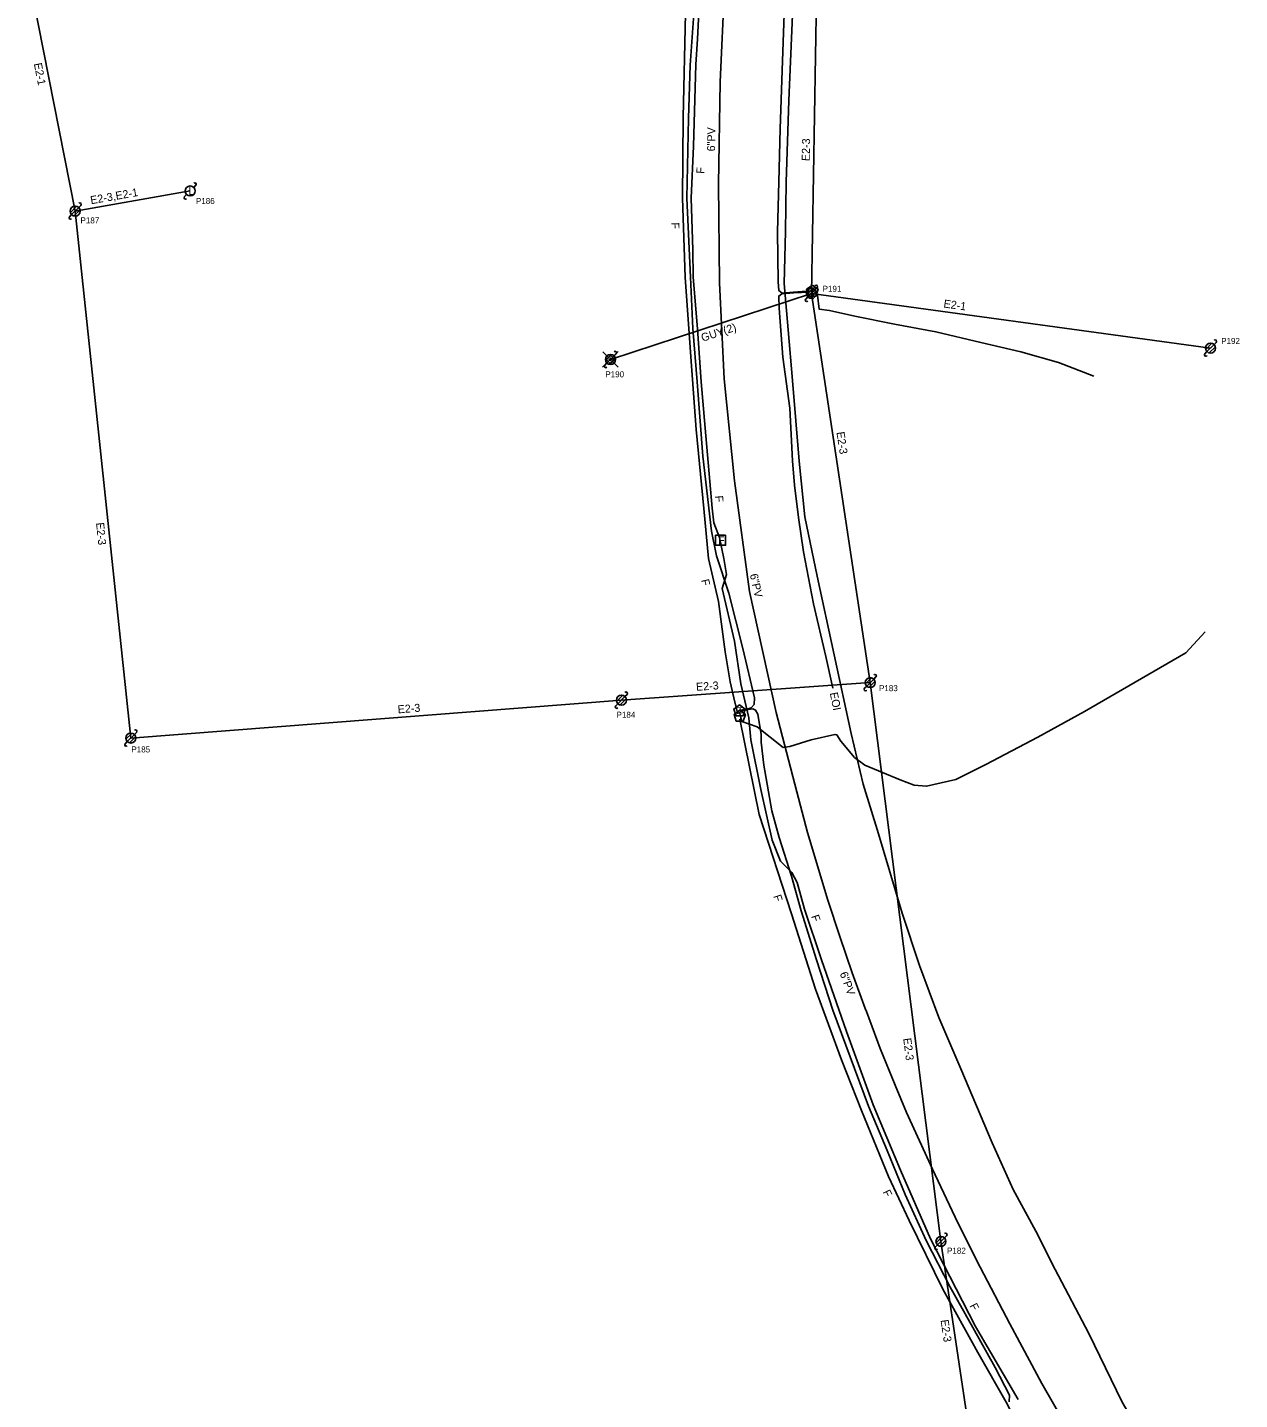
# Model space of a CAD drawing. Extents: x 1614474 to 1865144, y 1098877 to 1212550.
# Drawn here: x 1771681 to 1772286, y 1179760 to 1180446 of the extents above; entities that cross this region are included whole.
import ezdxf

# ---------------------------------------------------------------- set-up
doc = ezdxf.new("R2010")
doc.units = 0
for name, color, linetype in [('RD_EX_SU_H2O', 7, 'Continuous'), ('RD_EX_SU_Ovhd', 7, 'Continuous'), ('RD_EX_SU_Pole', 7, 'Continuous'), ('RD_EX_SU_Telecom', 7, 'Continuous'), ('RD_EX_SU_TX_H2O', 7, 'Continuous'), ('RD_EX_SU_TX_Pole', 7, 'Continuous'), ('RD_EX_SU_TX_Telecom', 7, 'Continuous')]:
    doc.layers.add(name, color=color, linetype=linetype)

# ---------------------------------------------------------------- blocks, each defined once
blk = doc.blocks.new('SUE_TPP')
at = {"layer": 'RD_EX_SU_Telecom'}
blk.add_lwpolyline([(0, 3), (-2.85, 0.93), (-1.76, -2.43), (1.76, -2.43), (2.85, 0.93)], close=True, dxfattribs=at)
blk.add_text('T', height=3.75, dxfattribs=at).set_placement((-1.25, -1.88))
blk = doc.blocks.new('SUE_PP')
at = {"layer": 'RD_EX_SU_Pole'}
for p, q in [((-2.41, -0.65), (0.65, 2.41)), ((-1.77, -1.77), (1.77, 1.77)), ((-0.65, -2.41), (2.41, 0.65)), ((1.77, 1.77), (2.83, 2.83)), ((-2.83, -2.83), (-1.77, -1.77))]:
    blk.add_line(p, q, dxfattribs=at)
blk.add_circle((0, 0), 2.5, dxfattribs=at)
for centre, start, end in [((2.3, 3.36), 315, 135), ((-2.3, -3.36), 135, 315)]:
    blk.add_arc(centre, 0.75, start, end, dxfattribs=at)
blk = doc.blocks.new('SUE_PGP')
at = {"layer": 'RD_EX_SU_Pole'}
for p, q in [((-1.06, 1.06), (-3.89, 3.89)), ((1.02, 1.12), (3.86, 3.96)), ((-1.11, -1.04), (-3.94, -3.87)), ((1.06, -1.06), (3.89, -3.89))]:
    blk.add_line(p, q, dxfattribs=at)
for points in [[(0, -2.12), (2.12, 0), (0, 2.12), (-2.12, 0)], [(0, -0.71), (0.71, 0), (0, 0.71), (-0.71, 0)]]:
    blk.add_lwpolyline(points, close=True, dxfattribs=at)
blk = doc.blocks.new('SUE_TFOH')
at = {"layer": 'RD_EX_SU_Telecom'}
blk.add_lwpolyline([(2.5, 2.5), (-2.5, 2.5), (-2.5, -2.5), (2.5, -2.5)], close=True, dxfattribs=at)
blk.add_text('F', height=4, dxfattribs=at).set_placement((-1.24, -2))

msp = doc.modelspace()

# ---------------------------------------------------------------- linework, layer by layer
at = {"layer": 'RD_EX_SU_H2O'}
for points in [[(1771946.33, 1181096.31), (1771960.64, 1181055.82), (1771973.6, 1181008.54), (1771976.62, 1180996.3), (1771978.04, 1180990.49), (1771985.75, 1180959.54), (1771995.65, 1180911.92), (1772005.3, 1180861.73), (1772012.04, 1180824.37), (1772022.72, 1180767.33), (1772026.42, 1180743.62), (1772030.32, 1180722.72), (1772031.31, 1180715.87), (1772037.92, 1180673.78), (1772038.35, 1180664.76), (1772039.77, 1180619.55), (1772036.68, 1180566.85), (1772033.48, 1180542.16), (1772029.35, 1180479.91), (1772029.16, 1180466.1), (1772027.05, 1180418.5)], [(1772027.04, 1180418.41), (1772026.19, 1180367.49), (1772026.71, 1180318.08), (1772029.02, 1180270.07), (1772034.21, 1180219.13)], [(1772034.21, 1180219.13), (1772041.65, 1180163.88), (1772055.06, 1180103.38), (1772065.28, 1180063.73), (1772070.66, 1180043.43), (1772080.89, 1180009.53), (1772086.72, 1179991.37), (1772092.93, 1179973.33), (1772099.51, 1179955.44), (1772100.08, 1179953.93), (1772107.03, 1179935.49), (1772114.36, 1179917.15), (1772120.07, 1179903.57), (1772133.04, 1179875.19), (1772145.72, 1179848.35), (1772156.87, 1179826.17), (1772171.79, 1179797.91), (1772187.78, 1179767.99), (1772216.09, 1179718.41)]]:
    msp.add_lwpolyline(points, dxfattribs=at)
at = {"layer": 'RD_EX_SU_Ovhd'}
for p, q in [((1772072.6, 1180312.82), (1772076.21, 1180520.25)), ((1771681.02, 1180474.64), (1771704.86, 1180353.95)), ((1771704.86, 1180353.95), (1771762.29, 1180364)), ((1771704.86, 1180353.95), (1771732.64, 1180090.63)), ((1771972.25, 1180279.81), (1772072.6, 1180312.82)), ((1772072.6, 1180312.82), (1772271.97, 1180285.51)), ((1772072.6, 1180312.82), (1772101.99, 1180118.32)), ((1771977.69, 1180109.55), (1772101.99, 1180118.32)), ((1772101.99, 1180118.32), (1772137.33, 1179839.06)), ((1771732.64, 1180090.63), (1771977.69, 1180109.55)), ((1772137.33, 1179839.06), (1772151.25, 1179745.42))]:
    msp.add_line(p, q, dxfattribs=at)
at = {"layer": 'RD_EX_SU_Pole'}
for p, q in [((1771764.06, 1180365.77), (1771765.12, 1180366.83)), ((1771759.47, 1180361.17), (1771760.53, 1180362.23)), ((1771969.83, 1180279.17), (1771972.89, 1180282.23)), ((1771970.48, 1180278.05), (1771974.02, 1180281.58)), ((1771974.02, 1180281.58), (1771975.08, 1180282.64)), ((1771969.42, 1180276.99), (1771970.48, 1180278.05)), ((1771971.6, 1180277.4), (1771974.66, 1180280.46)), ((1772099.57, 1180117.68), (1772102.64, 1180120.74)), ((1772100.22, 1180116.56), (1772103.76, 1180120.09)), ((1772101.34, 1180115.91), (1772104.4, 1180118.97)), ((1772103.76, 1180120.09), (1772104.82, 1180121.15)), ((1771975.27, 1180108.9), (1771978.33, 1180111.97)), ((1771975.92, 1180107.78), (1771979.45, 1180111.32)), ((1771977.04, 1180107.14), (1771980.1, 1180110.2)), ((1771979.45, 1180111.32), (1771980.52, 1180112.38)), ((1772099.16, 1180115.5), (1772100.22, 1180116.56)), ((1771974.86, 1180106.72), (1771975.92, 1180107.78)), ((1772134.5, 1179836.24), (1772135.56, 1179837.3)), ((1772134.92, 1179838.42), (1772137.98, 1179841.48)), ((1772135.56, 1179837.3), (1772139.1, 1179840.83)), ((1772136.68, 1179836.65), (1772139.75, 1179839.71)), ((1772139.1, 1179840.83), (1772140.16, 1179841.89))]:
    msp.add_line(p, q, dxfattribs=at)
for centre in [(1771762.29, 1180364), (1771972.25, 1180279.81), (1772101.99, 1180118.32), (1771977.69, 1180109.55), (1772137.33, 1179839.06)]:
    msp.add_circle(centre, 2.5, dxfattribs=at)
for centre, start, end in [((1771764.59, 1180367.36), 315, 135), ((1771760, 1180360.64), 135, 315), ((1771974.55, 1180283.17), 315, 135), ((1771969.95, 1180276.46), 135, 315), ((1772104.29, 1180121.68), 315, 135), ((1771979.98, 1180112.91), 315, 135), ((1772099.69, 1180114.97), 135, 315), ((1771975.39, 1180106.19), 135, 315), ((1772139.63, 1179842.42), 315, 135), ((1772135.03, 1179835.71), 135, 315)]:
    msp.add_arc(centre, 0.75, start, end, dxfattribs=at)
at = {"layer": 'RD_EX_SU_Telecom'}
for points in [[(1772012.4, 1180691.05), (1772014.96, 1180664.17), (1772016.98, 1180649.27), (1772018.9, 1180630.77), (1772019.09, 1180608.47), (1772017.52, 1180569.82), (1772016.3, 1180531.32), (1772014.96, 1180507.29), (1772011.23, 1180478.08), (1772009.64, 1180452.63), (1772008.51, 1180400.68), (1772008.17, 1180360.43), (1772009.54, 1180320.86), (1772012.41, 1180281.05), (1772014.97, 1180244.87), (1772018.85, 1180205.33), (1772021.16, 1180180.29), (1772026.12, 1180158.87), (1772029.53, 1180133.75), (1772032.05, 1180118.67), (1772034.35, 1180108.62), (1772035.86, 1180102.65)], [(1772020.81, 1180692.29), (1772021.27, 1180688.23), (1772021.68, 1180672.96), (1772022.14, 1180659.78), (1772024.54, 1180651), (1772025.43, 1180631.15), (1772025.9, 1180608.06), (1772025.16, 1180581.97), (1772024.46, 1180555.62), (1772022.98, 1180530.76), (1772021.28, 1180502.21), (1772017.52, 1180477.19), (1772015.73, 1180439.92), (1772014.84, 1180427.29), (1772013.76, 1180386.43), (1772012.51, 1180360.39), (1772013.33, 1180334.64), (1772013.48, 1180321.01), (1772015.66, 1180295.14), (1772017.49, 1180268.59), (1772019.54, 1180245.54), (1772022.98, 1180205.51), (1772023.89, 1180198.24), (1772026.76, 1180190.86)], [(1772093.26, 1180684.17), (1772093.78, 1180683.39), (1772093.38, 1180682.04), (1772091.18, 1180680.53), (1772089.29, 1180677.82), (1772084.23, 1180658.05), (1772080.74, 1180632.02), (1772076.55, 1180605.53), (1772072.26, 1180563.1), (1772068.53, 1180520.99), (1772064.99, 1180478.55), (1772063.24, 1180452.07), (1772061.27, 1180409.29), (1772060.04, 1180368.49), (1772059.73, 1180343.81), (1772059.04, 1180317.82), (1772061.04, 1180294.69), (1772063.08, 1180269.32), (1772066.45, 1180228.96), (1772069.24, 1180201.17), (1772075.4, 1180171.53)], [(1772013.83, 1180452.5), (1772011.97, 1180426.89), (1772011.14, 1180400.34), (1772010.39, 1180360.42), (1772012.2, 1180320.95), (1772013.39, 1180295.36), (1772015.5, 1180268.6), (1772018.39, 1180231.42), (1772022.7, 1180193.97), (1772025.18, 1180181.67), (1772031.3, 1180163.03), (1772038.39, 1180135.42), (1772044.2, 1180110.69), (1772044, 1180107.37), (1772042.49, 1180105.71), (1772040.31, 1180105.13), (1772037.14, 1180104.49)], [(1772059.04, 1180452.51), (1772058.05, 1180424.17), (1772057.04, 1180395.13), (1772056.26, 1180368.64), (1772055.61, 1180343.58), (1772055.96, 1180318.59), (1772056.38, 1180314.23), (1772058.08, 1180313), (1772063.72, 1180313.39), (1772072.32, 1180314.07)], [(1772071.62, 1180313.41), (1772063.8, 1180313.15), (1772057.87, 1180312.6), (1772056.32, 1180311.51), (1772056.45, 1180305.45), (1772058.38, 1180281.01), (1772061.9, 1180255.49), (1772063.18, 1180229.19), (1772064.19, 1180217.02), (1772066.09, 1180200.88), (1772068.63, 1180183.6), (1772073.62, 1180157.71), (1772079.85, 1180131.3), (1772083.36, 1180115.57)], [(1772073.65, 1180313.94), (1772075.68, 1180311.95), (1772076.43, 1180304.98), (1772081.58, 1180304.26), (1772094.3, 1180301.39), (1772114.1, 1180297.53), (1772134.8, 1180293.68), (1772157.22, 1180288.35), (1772177.23, 1180283.56), (1772196.03, 1180278.36), (1772213.71, 1180271.52)], [(1772026.76, 1180190.86), (1772028.89, 1180180.31), (1772030.18, 1180172.35), (1772028.05, 1180165.42), (1772034.24, 1180138.98), (1772037.31, 1180117.65), (1772041.38, 1180100.71), (1772042.38, 1180089.81), (1772047.38, 1180064.95), (1772052.98, 1180039.64), (1772057.2, 1180029.06), (1772062.87, 1180023.41), (1772065.54, 1180018.36), (1772069.16, 1180005.09), (1772077.59, 1179979.83), (1772090.06, 1179944.01), (1772103.41, 1179907.34), (1772117.04, 1179874.61), (1772132.06, 1179840.41), (1772154.61, 1179796.55), (1772175.85, 1179760.01)], [(1772075.4, 1180171.53), (1772084, 1180132.22), (1772092.38, 1180092.84), (1772098.44, 1180067.59), (1772106.17, 1180042.75), (1772117.88, 1180003.06), (1772126.64, 1179976.91), (1772136.25, 1179950.98), (1772147.19, 1179925.3), (1772162.86, 1179888.41), (1772173.36, 1179865.06), (1772184.66, 1179844.24), (1772194.32, 1179824.98), (1772211.16, 1179792.98), (1772227.79, 1179758.82), (1772239.17, 1179739.37), (1772238.5, 1179735.61)], [(1772036.68, 1180103.56), (1772037.39, 1180100.93), (1772037.89, 1180098.84), (1772045.45, 1180096.15), (1772058.57, 1180085.93), (1772061.77, 1180086.48), (1772072.5, 1180089.69), (1772084.36, 1180092.41), (1772085.37, 1180092.18), (1772087.37, 1180089.03), (1772094.21, 1180080.96), (1772099.32, 1180077), (1772116.98, 1180069.69), (1772123.9, 1180067.1), (1772130.15, 1180066.52), (1772144.67, 1180069.87), (1772159.76, 1180077.45), (1772185.65, 1180091.13), (1772208.99, 1180103.92), (1772259.55, 1180133.19), (1772269.24, 1180143.68)], [(1772037.11, 1180104.08), (1772039.97, 1180104.78), (1772043.28, 1180105.25), (1772044.75, 1180104.6), (1772045.77, 1180102.55), (1772047.53, 1180092.46), (1772047.43, 1180088.63), (1772048.83, 1180077.11), (1772052.81, 1180054.25), (1772056.56, 1180040.94), (1772062.63, 1180021.54), (1772067.42, 1180004.29), (1772075.12, 1179979.77), (1772083.23, 1179954.62), (1772091.94, 1179931.36), (1772101.14, 1179906.64), (1772110.52, 1179884.48), (1772119.41, 1179862.58), (1772129.98, 1179839.55), (1772141.82, 1179816.59), (1772153.19, 1179796.07), (1772164.43, 1179776.09), (1772171.58, 1179762.18), (1772171.44, 1179758.91)], [(1772036.84, 1180100.1), (1772046.54, 1180052.39), (1772062.7, 1180002.85), (1772074.67, 1179965.1), (1772087.57, 1179929.86), (1772097.64, 1179904.56), (1772111.08, 1179871.59), (1772121.41, 1179849.51), (1772138.33, 1179815.14), (1772155.74, 1179783.62), (1772169.95, 1179758.69), (1772179.21, 1179740.8), (1772194.1, 1179712.23), (1772207.79, 1179687.12), (1772218.45, 1179667.81), (1772229.28, 1179650.86), (1772242.54, 1179625.6), (1772258.24, 1179598.97), (1772267.73, 1179581.63), (1772277.86, 1179560.41), (1772279.28, 1179554.65), (1772279.32, 1179549.33)]]:
    msp.add_lwpolyline(points, dxfattribs=at)

# ---------------------------------------------------------------- block references
at = {"layer": 'RD_EX_SU_Pole'}
for name, p in [('SUE_PP', (1771704.86, 1180353.95)), ('SUE_PP', (1772072.6, 1180312.82)), ('SUE_PP', (1772271.97, 1180285.51)), ('SUE_PGP', (1771972.25, 1180279.81)), ('SUE_PP', (1771732.64, 1180090.63))]:
    msp.add_blockref(name, p, dxfattribs=at)
at = {"layer": 'RD_EX_SU_Telecom'}
for name, p in [('SUE_TPP', (1772073.08, 1180313.93)), ('SUE_TFOH', (1772027.2, 1180189.44)), ('SUE_TPP', (1772036.7, 1180104.18)), ('SUE_TPP', (1772036.82, 1180101.49))]:
    msp.add_blockref(name, p, dxfattribs=at)

# ---------------------------------------------------------------- texts
at = {"layer": 'RD_EX_SU_Ovhd'}
for s, rotation, p in [('E2-1', 281.17131, (1771684.19, 1180427.61)), ('E2-3', 89.00406, (1772071.75, 1180378.93)), ('E2-3,E2-1', 9.92754, (1771712.79, 1180357.37)), ('E2-1', 352.20119, (1772138.43, 1180305.82)), ('GUY(2)', 18.20387, (1772018.27, 1180288.63)), ('E2-3', 278.5927, (1772085.11, 1180243.42)), ('E2-3', 276.02388, (1771715.27, 1180198.13)), ('E2-3', 4.03673, (1772015.12, 1180114.2)), ('E2-3', 4.41569, (1771866.1, 1180102.94)), ('E2-3', 277.21305, (1772118.45, 1179940.48)), ('E2-3', 278.45678, (1772137.11, 1179799.72))]:
    msp.add_text(s, height=4, rotation=rotation, dxfattribs=at).set_placement(p)
at = {"layer": 'RD_EX_SU_Pole'}
msp.add_text('L', height=4, dxfattribs=at).set_placement((1771761.43, 1180362))
at = {"layer": 'RD_EX_SU_TX_H2O'}
for rotation, p in [(89.04401, (1772024.46, 1180383.77)), (282.49643, (1772041.83, 1180172.3)), (290.18528, (1772086.67, 1179972.98))]:
    msp.add_text('6"PV', height=4, rotation=rotation, dxfattribs=at).set_placement(p)
at = {"layer": 'RD_EX_SU_TX_Pole'}
for s, p in [('P186', (1771765.18, 1180357.5)), ('P187', (1771707.52, 1180347.81)), ('P191', (1772078.2, 1180313.64)), ('P192', (1772277.29, 1180287.57)), ('P190', (1771969.67, 1180270.92)), ('P183', (1772106.37, 1180114.05)), ('P184', (1771975.27, 1180100.76)), ('P185', (1771732.94, 1180083.43)), ('P182', (1772140.36, 1179832.97))]:
    msp.add_text(s, height=3, dxfattribs=at).set_placement(p)
at = {"layer": 'RD_EX_SU_TX_Telecom'}
for s, rotation, p in [('F', 87.26206, (1772019.1, 1180372.55)), ('F', 271.98212, (1772002.59, 1180348.24)), ('F', 274.90977, (1772024.46, 1180211.64)), ('F', 283.03161, (1772017.48, 1180169.57)), ('EOI', 281.54006, (1772081.76, 1180113.1)), ('F', 288.07074, (1772053.52, 1180011.63)), ('F', 288.45142, (1772072.44, 1180001.56)), ('F', 295.06055, (1772108.11, 1179863.77)), ('F', 297.21549, (1772151.52, 1179806.95))]:
    msp.add_text(s, height=4, rotation=rotation, dxfattribs=at).set_placement(p)

doc.saveas('drawing.dxf')
